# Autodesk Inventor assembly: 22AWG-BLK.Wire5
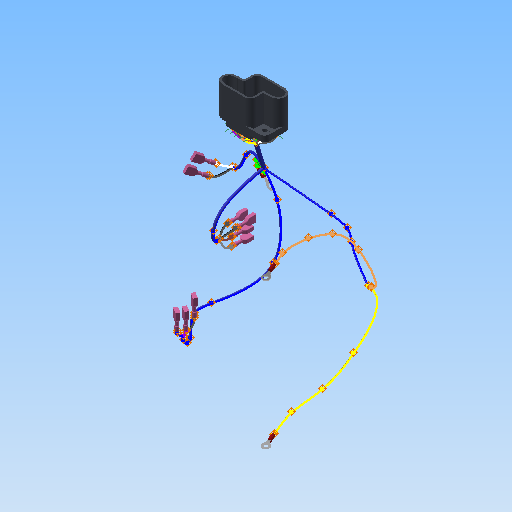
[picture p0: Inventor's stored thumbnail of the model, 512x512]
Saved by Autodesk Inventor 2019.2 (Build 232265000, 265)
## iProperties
Created: 2006-02
Part Number: 22AWG-BLK.Wire5
Description: 22AWG-BLK
Designer: floress
Stock Number: 22AWG-BLK
Material: Default
Author: floress
Part Number: 22AWG-ORG.Wire9
Description: 22AWG-ORG
Stock Number: 22AWG-ORG
Part Number: 18AWG-GRN.Wire4
Description: 18AWG-GRN
Stock Number: 18AWG-GRN
Part Number: 22AWG-YEL.Wire8
Description: 22AWG-YEL
Stock Number: 22AWG-YEL
Part Number: 18AWG-BLK.Wire2
Description: 18AWG-BLK
Stock Number: 18AWG-BLK
Part Number: 18AWG-BLK.Wire1
Part Number: 18AWG-WHT.Wire3
Description: 18AWG-WHT
Stock Number: 18AWG-WHT
ParentFileIdentifier: 5|1|0|0|144|1|0|0|80|0|65|0|84|0|72|0|83|0|59|0|67|0|58|0|92|0|77|0|121|0|32|0|68|0|111|0|99|0|117|0|109|0|101|0|110|0|116|0|115|0|92|0|73|0|110|0|118|0|101|0|1
Part Number: 22AWG-GRY.Wire11
Description: 22AWG-GRY
Stock Number: 22AWG-GRY
Part Number: 22AWG-VIO.Wire7
Description: 22AWG-VIO
Stock Number: 22AWG-VIO
Part Number: 22AWG-BLU.Wire6
Description: 22AWG-BLU
Stock Number: 22AWG-BLU
Part Number: 22AWG-BRN.Wire10
Description: 22AWG-BRN
Stock Number: 22AWG-BRN
Created: 2005-11
Part Number: Hopper.Harness1
Document SubType Name: Assembly
HarnessSettings: <HarnessSettings><Defaults><Segments><Diameter value="0.200 in" fromwires="True"/><Offset value="0.100 in"/><ColorStyle value="Blue"/><RoundUp value=""/><BendRa
CableFileVersion: 11.0.9
CableDummyParamRefKey: Key:16|2|0|0|16|0|0|0|246|63|0|0|0|0|0|0|129|0|0|0|0|0|0|0|Level:1
GlobalPropertyList: <PropertyList/>
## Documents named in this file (5)
- D:\Slotmachine\Workspaces\Workspace\Cabinet\Hopper\AIP\Cable and Harness\Hopper.Harness1.iam
- D:\Slotmachine\Workspaces\Workspace\Cabinet\Hopper\AIP\Cable and Harness\Hopper.Harness1.ipt
- D:\Slotmachine\Workspaces\Workspace\Hardware\Connectors\Terminal Ring.ipt
- D:\Slotmachine\Workspaces\Workspace\Hardware\Connectors\Quick Connect, Female, 22AWG.ipt
- D:\Slotmachine\Workspaces\Workspace\Hardware\Connectors\A208209-1.ipt
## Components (25 placed, 15 different names)
1. A208209-1:1
2. Terminal Ring:1
3. Terminal Ring:2
4. Terminal Ring:3
5. Quick Connect, Female, 22AWG:1
6. Quick Connect, Female, 22AWG:2
7. Quick Connect, Female, 22AWG:3
8. Quick Connect, Female, 22AWG:4
9. Quick Connect, Female, 22AWG:5
10. Quick Connect, Female, 22AWG:6
11. Quick Connect, Female, 22AWG:7
12. Quick Connect, Female, 22AWG:8
13. Quick Connect, Female, 22AWG:9
14. Harness1
15. HA_VC_111:1
16. HA_VC_123:1
17. HA_VC_126:1
18. HA_VC_225:1
19. HA_VC_228:1
20. HA_VC_231:1
21. HA_VC_234:1
22. HA_VC_237:1
23. HA_VC_240:1
24. HA_VC_243:1
25. HA_VC_246:1
